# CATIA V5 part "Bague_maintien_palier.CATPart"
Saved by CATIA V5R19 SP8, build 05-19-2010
Part number: Bague_maintien_palier
Bounding box of the stored display mesh (mm): x -50 to 50, y -50 to 50, z 0 to 3
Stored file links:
  G:\EU_thinkMotion\CFAO_2010\MMS_groupe1\MMS_groupe1\OK\vduret\vduret\CATIA\Bague_maintien_palier.CATPart
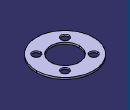
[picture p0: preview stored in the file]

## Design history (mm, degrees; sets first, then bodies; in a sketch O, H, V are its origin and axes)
Body1 (main body)
  Sketch1 on xy-plane, origin (0, 0, 0), H (1, 0, 0), V (0, 1, 0)
    circle A1 centre (0, 0) radius 50
    circle A2 centre (25, 25) radius 7
    point P1 (25, 25)
    circle A3 centre (25, -25) radius 7
    circle A4 centre (-25, 25) radius 7
    circle A5 centre (-25, -25) radius 7
    circle A6 centre (0, 0) radius 25
    radius A1 = 50
    radius A2 = 7
    distance P1 H = 25
    distance P1 V = 25
    radius A6 = 25
    symmetry: A2 A3 H, A2 A4 V, A3 A5 V
  Pad1: profile Sketch1, direction (0, 0, 1), length 3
